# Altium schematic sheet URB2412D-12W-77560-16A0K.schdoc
size 277 x 190 mm; Device: default297x210; Symbol: default297x210; Name: default297x210; Size: "A4"; Id: /; File: URB2412D-12W-77560-16A0K; Sheet: /
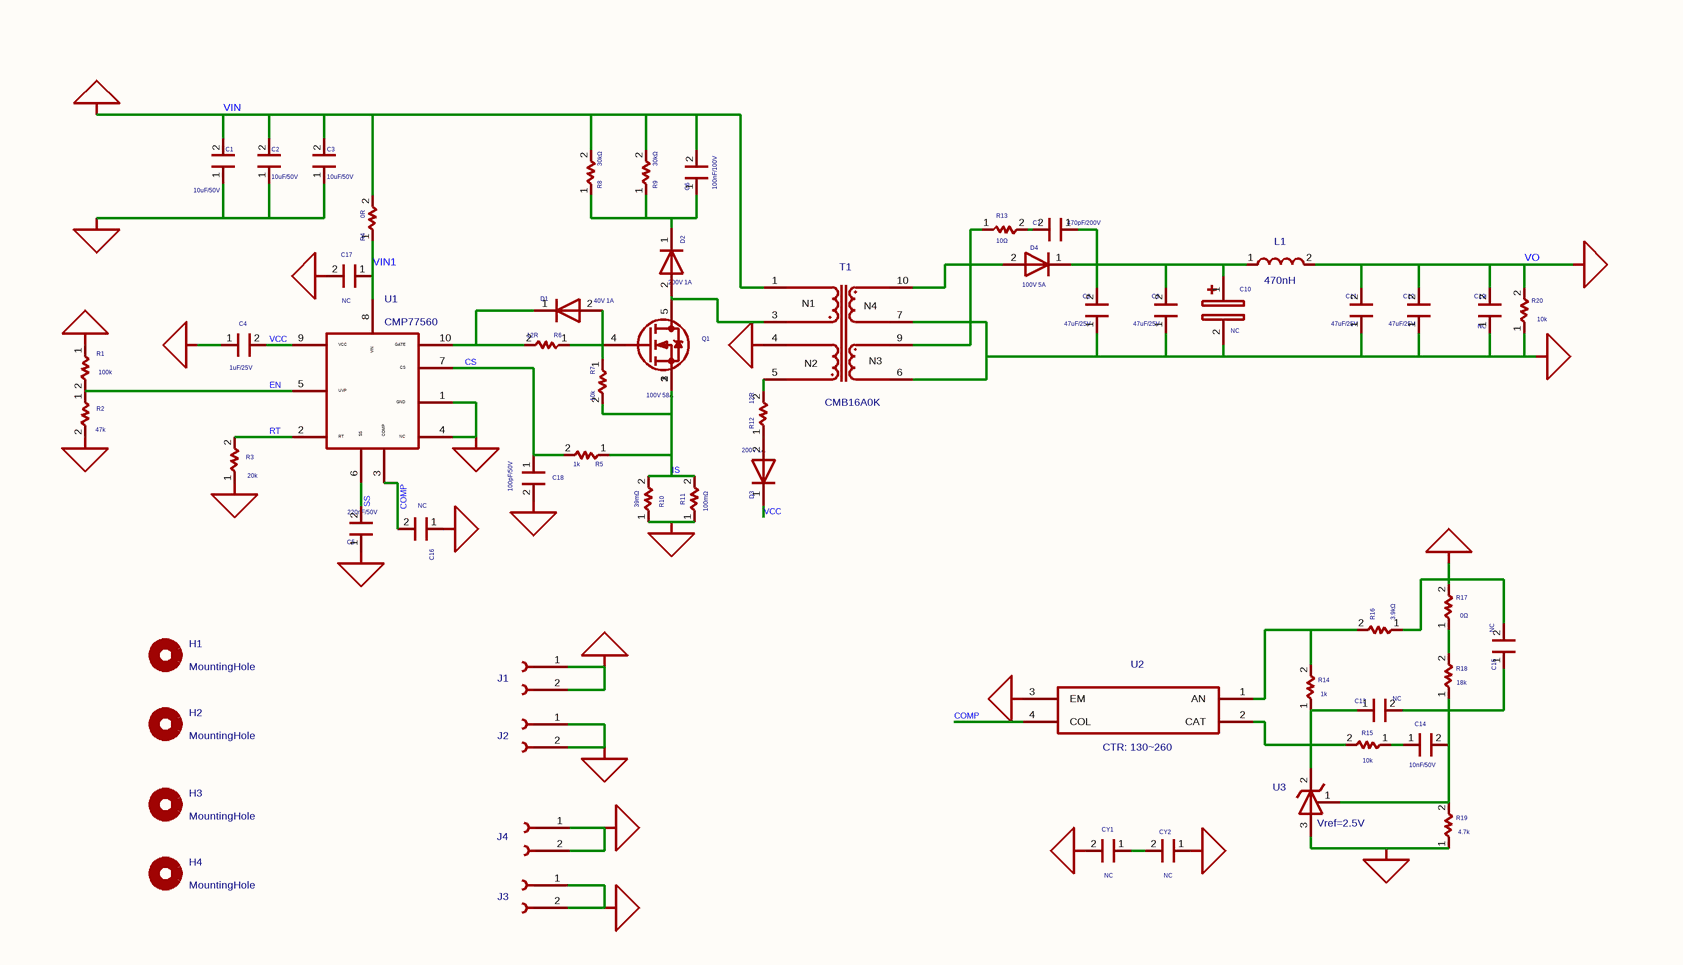
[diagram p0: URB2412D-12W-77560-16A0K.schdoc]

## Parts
C1  value 10uF/50V  [MYLibrary:C1206A]  (hidden comment: Coileasy library_C)
C2  value 10uF/50V  [MYLibrary:C1206A]  (hidden comment: Coileasy library_C)
C3  value 10uF/50V  [MYLibrary:C1206A]  (hidden comment: Coileasy library_C)
C4  value 1uF/25V  [MYLibrary:C0603]  (hidden comment: Coileasy library_C)
C5  value 220nF/50V  [MYLibrary:C0603]  (hidden comment: Coileasy library_C)
C6  value 100nF/100V  [MYLibrary:C0805]  (hidden comment: Coileasy library_C)
C7  value 470pF/200V  [MYLibrary:C0805]  (hidden comment: Coileasy library_C)
C8  value 47uF/25V  [MYLibrary:C1206A]  (hidden comment: Coileasy library_C)
C9  value 47uF/25V  [MYLibrary:C1206A]  (hidden comment: Coileasy library_C)
C10  value NC  [Capacitor_THT:CP_Radial_D8.0mm_P3.50mm]  (hidden comment: Device_C_Polarized)
C11  value 47uF/25V  [MYLibrary:C1206A]  (hidden comment: Coileasy library_C)
C12  value 47uF/25V  [MYLibrary:C1206A]  (hidden comment: Coileasy library_C)
C13  value NC  [MYLibrary:C0603]  (hidden comment: Coileasy library_C)
C14  value 10nF/50V  [MYLibrary:C0603]  (hidden comment: Coileasy library_C)
C15  value NC  [MYLibrary:C0603]  (hidden comment: Coileasy library_C)
C16  value NC  [MYLibrary:C0603]  (hidden comment: Coileasy library_C)
C17  value NC  [MYLibrary:C0603]  (hidden comment: Coileasy library_C)
C18  value 100pF/50V  [MYLibrary:C0603]  (hidden comment: Coileasy library_C)
C19  value NC  [MYLibrary:C0603]  (hidden comment: Coileasy library_C)
CY1  value NC  [MYLibrary:C1206]  (hidden comment: Coileasy library_C)
CY2  value NC  [MYLibrary:C1206]  (hidden comment: Coileasy library_C)
D1  value 40V 1A  [Diode_SMD:D_SOD-323_HandSoldering]  (hidden comment: Coileasy library_D)
D2  value 200V 1A  [MYLibrary:SOD-123-323]  (hidden comment: Coileasy library_D)
D3  value 200V 1A  [MYLibrary:SOD-123-323]  (hidden comment: Coileasy library_D)
D4  value 100V 5A  [Diode_SMD:D_PowerDI-5]  (hidden comment: Device_D)
H1  value MountingHole  [MountingHole:MountingHole_3.2mm_M3]  (hidden comment: Mechanical_MountingHole)
H2  value MountingHole  [MountingHole:MountingHole_3.2mm_M3]  (hidden comment: Mechanical_MountingHole)
H3  value MountingHole  [MountingHole:MountingHole_3.2mm_M3]  (hidden comment: Mechanical_MountingHole)
H4  value MountingHole  [MountingHole:MountingHole_3.2mm_M3]  (hidden comment: Mechanical_MountingHole)
J1  Coileasy library_Conn_01x02  [Connector_PinHeader_2.54mm:PinHeader_1x02_P2.54mm_Vertical]  (value not drawn)
J2  Coileasy library_Conn_01x02  [Connector_PinHeader_2.54mm:PinHeader_1x02_P2.54mm_Vertical]  (value not drawn)
J3  Coileasy library_Conn_01x02  [Connector_PinHeader_2.54mm:PinHeader_1x02_P2.54mm_Vertical]  (value not drawn)
J4  Coileasy library_Conn_01x02  [Connector_PinHeader_2.54mm:PinHeader_1x02_P2.54mm_Vertical]  (value not drawn)
L1  value 470nH  [Inductor_SMD:L_APV_ANR4018]  (hidden comment: Device_L)
Q1  value 100V 58A  [Package_TO_SOT_SMD:TDSON-8-1]  (hidden comment: Transistor_FET_BSC026N08NS5)
R1  value 100k  [MYLibrary:R0603]  (hidden comment: Coileasy library_R)
R2  value 47k  [MYLibrary:R0603]  (hidden comment: Coileasy library_R)
R3  value 20k  [MYLibrary:R0603]  (hidden comment: Coileasy library_R)
R4  value 0R  [MYLibrary:R0603]  (hidden comment: Coileasy library_R)
R5  value 1k  [MYLibrary:R0603]  (hidden comment: Coileasy library_R)
R6  value 12R  [MYLibrary:R0603]  (hidden comment: Coileasy library_R)
R7  value 10k  [MYLibrary:R0603]  (hidden comment: Coileasy library_R)
R8  value 30kΩ  [MYLibrary:R1206A]  (hidden comment: Coileasy library_R)
R9  value 30kΩ  [MYLibrary:R1206A]  (hidden comment: Coileasy library_R)
R10  value 39mΩ  [MYLibrary:R1206]  (hidden comment: Coileasy library_R)
R11  value 100mΩ  [MYLibrary:R1206]  (hidden comment: Coileasy library_R)
R12  value 12R  [coileasy:R_0603]  (hidden comment: Coileasy library_R)
R13  value 10Ω  [MYLibrary:R1206A]  (hidden comment: Coileasy library_R)
R14  value 1k  [MYLibrary:R0603]  (hidden comment: Coileasy library_R)
R15  value 10k  [MYLibrary:R0603]  (hidden comment: Coileasy library_R)
R16  value 3.9kΩ  [MYLibrary:R0603]  (hidden comment: Coileasy library_R)
R17  value 0Ω  [MYLibrary:R0603]  (hidden comment: Coileasy library_R)
R18  value 18k  [MYLibrary:R0603]  (hidden comment: Coileasy library_R)
R19  value 4.7k  [MYLibrary:R0603]  (hidden comment: Coileasy library_R)
R20  value 10k  [MYLibrary:R0603]  (hidden comment: Coileasy library_R)
T1  value CMB16A0K  [MYLibrary:EP13]  (hidden comment: MYLibrary_CMB4+4)
U1  value CMP77560  [Package_SO:MSOP-10_3x3mm_P0.5mm]  (hidden comment: MYLibrary_CMP7756X)
U2  value CTR: 130~260  [kicad_community_lib:PC817B__Slkor]  (hidden comment: PC817B__Slkor_PC817B__Slkor)
U3  value Vref=2.5V  [Package_TO_SOT_SMD:SOT-23]  (hidden comment: Coileasy library_CJ431)

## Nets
GND1: C1.1 C2.1 C3.1 C4.1 C5.1 C16.1 C17.2 C18.2 CY1.2 J2.1(Pin_1) J2.2(Pin_2) R2.2 R3.1 R10.1 R11.1 T1.4 U1.1(GND) U1.4(NC) U2.3(EM)
GND2: C8.1 C9.1 C10.2 C11.1 C12.1 C19.1 CY2.1 J3.1(Pin_1) J3.2(Pin_2) R19.1 R20.1 T1.6 T1.7 U3.3
VIN: C1.2 C2.2 C3.2 C6.2 J1.1(Pin_1) J1.2(Pin_2) R1.1 R4.2 R8.2 R9.2 T1.1
VO: C11.2 C12.2 C15.2 C19.2 J4.1(Pin_1) J4.2(Pin_2) L1.2 R16.1 R17.2 R20.2
COMP: C16.2 U1.3(COMP) U2.4(COL)
CS: C18.1 R5.2 U1.7(CS)
EN: R1.2 R2.1 U1.5(UVP)
IS: Q1.1(S) Q1.2(S) Q1.3(S) R5.1 R7.2 R10.2 R11.2
RT: R3.2 U1.2(RT)
SS: C5.2 U1.6(SS)
VCC: C4.2 D3.1(K) U1.9(VCC)
VIN1: C17.1 R4.1 U1.8(VIN)
NetC6_1: C6.1 D2.1(K) R8.1 R9.1
NetC7_1: C7.1 C8.2 C9.2 C10.1 D4.1(K) L1.1
NetC7_2: C7.2 R13.2
NetC13_1: C13.1 R14.1 R15.2 U2.2(CAT) U3.2
NetC13_2: C13.2 C14.2 C15.1 R18.1 R19.2 U3.1
NetC14_1: C14.1 R15.1
NetCY1_1: CY1.1 CY2.2
NetD1_1: D1.1(K) R6.2 U1.10(GATE)
NetD1_2: D1.2(A) Q1.4(G) R6.1 R7.1
NetD2_2: D2.2(A) Q1.5(D) T1.3
NetD3_2: D3.2(A) R12.1
NetD4_2: D4.2(A) R13.1 T1.9 T1.10
NetR12_2: R12.2 T1.5
NetR14_2: R14.2 R16.2 U2.1(AN)
NetR17_1: R17.1 R18.2

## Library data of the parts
C1-C3 = Coileasy library_C: 10uF/50V-X5R; Brand: FH; Model: 1206X106K500NT; ki_keywords: cap capacitor; ki_fp_filters: C_*; Attribute1: C2; AddInBom: yes
C4 = Coileasy library_C: 1uF/25V-X7R; Brand: FH; Model: 0603B105K250NT; ki_keywords: cap capacitor; ki_fp_filters: C_*; UniqueId: 623e2bb2442f04df; Attribute1: C4; AddInBom: yes
C5 = Coileasy library_C: 220nF/50V-X7R; Brand: FH; Model: 0603B224K500NT; ki_keywords: cap capacitor; ki_fp_filters: C_*; UniqueId: 05d417a4d81547fc; Attribute1: C4; AddInBom: yes
C6 = Coileasy library_C: 100nF/100V-X7R; Brand: FH; Model: 0805B104K101NT; ki_keywords: cap capacitor; ki_fp_filters: C_*; Attribute1: C6; AddInBom: yes
C7 = Coileasy library_C: 470pF/200V-X7R; Brand: YAGEO; Model: CC0805JRX7RABB471; ki_keywords: cap capacitor; ki_fp_filters: C_*; UniqueId: 3007ca2539a35480; Attribute1: C6; AddInBom: yes
C8 = Coileasy library_C: 47uF/25V-X5R; Brand: TDK; Model: C3216X5R1E476MTJ00E; ki_keywords: cap capacitor; ki_fp_filters: C_*; UniqueId: 878ab3ab0cce2757; Attribute1: C2; AddInBom: yes
C9 = Coileasy library_C: 47uF/25V-X5R; Brand: TDK; Model: C3216X5R1E476MTJ00E; ki_keywords: cap capacitor; ki_fp_filters: C_*; UniqueId: 60e6893b044e2f17; Attribute1: C2; AddInBom: yes
C10 = Device_C_Polarized: NC; Add into BOM: no; ki_keywords: cap capacitor; ki_fp_filters: CP_*; UniqueId: c1764753ee6525b4; Attribute1: C10
C11 = Coileasy library_C: 47uF/25V-X5R; Brand: TDK; Model: C3216X5R1E476MTJ00E; ki_keywords: cap capacitor; ki_fp_filters: C_*; UniqueId: b49c3108c5288e9f; Attribute1: C2; AddInBom: yes
C12 = Coileasy library_C: 47uF/25V-X5R; Brand: TDK; Model: C3216X5R1E476MTJ00E; ki_keywords: cap capacitor; ki_fp_filters: C_*; UniqueId: 4eba2014d94c20ef; Attribute1: C2; AddInBom: yes
C13 C15 = Coileasy library_C: NC; Add into BOM: no; ki_keywords: cap capacitor; ki_fp_filters: C_*; Attribute1: C4
C14 = Coileasy library_C: 10nF/50V-X7R; Brand: FH; Model: 0603B103K500NT; ki_keywords: cap capacitor; ki_fp_filters: C_*; Attribute1: C4; AddInBom: yes
C16 = Coileasy library_C: NC; Add into BOM: no; ki_keywords: cap capacitor; ki_fp_filters: C_*; UniqueId: 6992a3033003bbbd; Attribute1: C4
C17 = Coileasy library_C: NC; Add into BOM: no; ki_keywords: cap capacitor; ki_fp_filters: C_*; UniqueId: 5e7964c847a08933; Attribute1: C4
C18 = Coileasy library_C: 100pF/50V-X7R; Brand: FH; Model: 0603B101K500NT; ki_keywords: cap capacitor; ki_fp_filters: C_*; UniqueId: 9b976857f3e39318; Attribute1: C4; AddInBom: yes
C19 = Coileasy library_C: NC; ki_keywords: cap capacitor; ki_fp_filters: C_*; UniqueId: 7dc0401965f49c44; Attribute1: C4; AddInBom: yes
CY1 CY2 = Coileasy library_C: NC; Add into BOM: no; ki_keywords: cap capacitor; ki_fp_filters: C_*; Attribute1: CY2
D1 = Coileasy library_D: 40V 1A; Brand: MDD; Model: B5819WS; ki_keywords: diode; ki_fp_filters: TO-???* *_Diode_* *SingleDiode* D_*; UniqueId: 07a0d5848cd81316; Attribute1: D1; AddInBom: yes
D2 = Coileasy library_D: 200V 1A; Brand: MDD; Model: DSK120; ki_keywords: diode; ki_fp_filters: TO-???* *_Diode_* *SingleDiode* D_*; UniqueId: fa5cd661465da5bc; Attribute1: D3; AddInBom: yes
D3 = Coileasy library_D: 200V 1A; Brand: MDD; Model: DSK120; ki_keywords: diode; ki_fp_filters: TO-???* *_Diode_* *SingleDiode* D_*; UniqueId: ce0e29427420bb9a; Attribute1: D3; AddInBom: yes
D4 = Device_D: 100V 5A; Sim.Device: D; Sim.Pins: 1=K 2=A; Brand: YANGJIE; Model: SS5U100; ki_keywords: diode; ki_fp_filters: TO-???* *_Diode_* *SingleDiode* D_*; UniqueId: 671e3575a93d22ee; Attribute1: D4; AddInBom: yes
H1-H4 = Mechanical_MountingHole: Mounting Hole without connection; ki_fp_filters: MountingHole*; Attribute1: H4; AddInBom: yes
J1-J4 = Coileasy library_Conn_01x02: ki_keywords: connector; ki_fp_filters: Connector*:*_1x??_*; Origin Footprint: library:PinHeader_1x02_P2.54mm_Vertical; Attribute1: J4; AddInBom: yes
L1 = Device_L: 470nH; Brand: YAGEO; Model: FNR4018SR47NT; ki_keywords: inductor choke coil reactor magnetic; ki_fp_filters: Choke_* *Coil* Inductor_* L_*; UniqueId: 2f42939b1ffc8518; Attribute1: L1; AddInBom: yes
Q1 = Transistor_FET_BSC026N08NS5: 100V 58A; Brand: CRMICRO; Model: CRSM120N10L2; ki_keywords: OptiMOS Power MOSFET N-MOS; ki_fp_filters: TDSON*; UniqueId: 047b734180970fea; Attribute1: Q1; AddInBom: yes
R1 = Coileasy library_R: 100kΩ ±1% 100mW; Brand: YAGEO; Model: RC0603FR-07100KL; ki_keywords: R res resistor; ki_fp_filters: R_*; UniqueId: 4e166b190d4de1c3; Attribute1: R5; AddInBom: yes
R2 = Coileasy library_R: 47kΩ ±1% 100mW; Brand: YAGEO; Model: RC0603FR-0747KL; ki_keywords: R res resistor; ki_fp_filters: R_*; UniqueId: 06442d24ab060343; Attribute1: R5; AddInBom: yes
R3 = Coileasy library_R: 20kΩ ±1% 100mW; Brand: YAGEO; Model: RC0603FR-0720KL; ki_keywords: R res resistor; ki_fp_filters: R_*; UniqueId: 6e26aea592918673; Attribute1: R5; AddInBom: yes
R4 = Coileasy library_R: 0Ω ±1% 100mW; Brand: YAGEO; Model: RC0603FR-070RL; ki_keywords: R res resistor; ki_fp_filters: R_*; UniqueId: 49359f7360e76581; Attribute1: R5; AddInBom: yes
R5 = Coileasy library_R: 1kΩ ±1% 100mW; Brand: YAGEO; Model: RC0603FR-071KL; ki_keywords: R res resistor; ki_fp_filters: R_*; UniqueId: 96bd3269827a783e; Attribute1: R5; AddInBom: yes
R6 = Coileasy library_R: 12Ω ±1% 100mW; Brand: YAGEO; Model: RC0603FR-0712RL; ki_keywords: R res resistor; ki_fp_filters: R_*; UniqueId: c9a24d22ca7022dc; Attribute1: R5; AddInBom: yes
R7 = Coileasy library_R: 10kΩ ±1% 100mW; Brand: YAGEO; Model: RC0603FR-0710KL; ki_keywords: R res resistor; ki_fp_filters: R_*; UniqueId: 01f5c70ff2630ee7; Attribute1: R5; AddInBom: yes
R8 R9 = Coileasy library_R: 30kΩ ±1% 250mW; Brand: YAGEO; Model: RC1206FR-0730KL; ki_keywords: R res resistor; ki_fp_filters: R_*; AddInBom: yes
R10 = Coileasy library_R: 39mΩ ±1% 250mW; Brand: FH; Model: RBF-06SR039FT; ki_keywords: R res resistor; ki_fp_filters: R_*; UniqueId: 7663007c1f2bc029; AddInBom: yes
R11 = Coileasy library_R: 100mΩ ±1% 250mW; Brand: FH; Model: RTG06WR100FTG; ki_keywords: R res resistor; ki_fp_filters: R_*; UniqueId: 069ba0dc55a84bc8; AddInBom: yes
R12 = Coileasy library_R: 12Ω ±1% 100mW; Brand: YAGEO; Model: RC0603FR-0712RL; ki_keywords: R res resistor; ki_fp_filters: R_*; UniqueId: f574a6082c36e6cb; AddInBom: yes
R13 = Coileasy library_R: 10Ω ±1% 500mW; Brand: YAGEO; Model: RC1206FR-7W10RL; ki_keywords: R res resistor; ki_fp_filters: R_*; UniqueId: ff7631ddbc1e2fda; AddInBom: yes
R14 = Coileasy library_R: 1kΩ ±1% 100mW; Brand: YAGEO; Model: RC0603FR-071KL; ki_keywords: R res resistor; ki_fp_filters: R_*; Attribute1: R5; AddInBom: yes
R15 = Coileasy library_R: 10kΩ ±1% 100mW; Brand: YAGEO; Model: RC0603FR-0710KL; ki_keywords: R res resistor; ki_fp_filters: R_*; Attribute1: R5; AddInBom: yes
R16 = Coileasy library_R: 3.9kΩ ±1% 100mW; Brand: YAGEO; Model: RC0603FR-073K9L; ki_keywords: R res resistor; ki_fp_filters: R_*; Attribute1: R5; AddInBom: yes
R17 = Coileasy library_R: 220Ω ±1% 100mW; Brand: YAGEO; Model: RC0603FR-07220RL; ki_keywords: R res resistor; ki_fp_filters: R_*; Attribute1: R5; AddInBom: yes
R18 = Coileasy library_R: 15kΩ ±1% 100mW; Brand: YAGEO; Model: RC0603FR-0715KL; ki_keywords: R res resistor; ki_fp_filters: R_*; Attribute1: R5; AddInBom: yes
R19 = Coileasy library_R: 3kΩ ±1% 100mW; Brand: YAGEO; Model: RC0603FR-073KL; ki_keywords: R res resistor; ki_fp_filters: R_*; Attribute1: R5; AddInBom: yes
R20 = Coileasy library_R: 10kΩ ±1% 100mW; Brand: YAGEO; Model: RC0603FR-0710KL; ki_keywords: R res resistor; ki_fp_filters: R_*; UniqueId: 237b6fcbd18a81e0; Attribute1: R5; AddInBom: yes
T1 = MYLibrary_CMB4+4: Np:Ns=1:1  Lp=22uH; Brand: coileasy; UniqueId: cf2c480e5945250c; Attribute1: T1; AddInBom: yes
U1 = MYLibrary_CMP7756X: 电源管理芯片; Brand: coileasy; UniqueId: 48a4a086d8c42a18; Attribute1: U1; AddInBom: yes
U2 = PC817B__Slkor_PC817B__Slkor: CTR: 130~260; Manufacturer: Slkor; Collector Emitter Saturation Voltage: 100 mV @1mA,20mA; Current Transfer Ratio (Min): 130 %; Forward Current: 50 mA; Forward Voltage: 1.2 V; Isolation Voltage: 5 kV; Number of Outputs: 1 defualt; Output Type: 光电三极管; Output Voltage: 35 V; Power Rating: 200 mW; Reverse Voltage: 6 V; Brand: LITEON; Model: LTV-816S-TA1-B; AddInBom: yes
U3 = Coileasy library_CJ431: Vref=2.5V; Brand: CJ; Model: CJ431; ki_keywords: diode; ki_fp_filters: TO-???* *_Diode_* *SingleDiode* D_*; Attribute1: U3; AddInBom: yes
